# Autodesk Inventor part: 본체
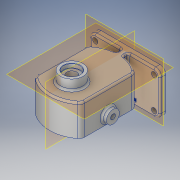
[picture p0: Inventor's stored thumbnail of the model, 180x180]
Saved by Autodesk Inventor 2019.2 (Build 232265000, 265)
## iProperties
Created: 2019-03
Part Number: 본체
Material: 알루미늄 6061
Document SubType Name: Modeling
Designer: User
Density: 2.7 g/cm^3
Appearance: 알루미늄 - 평지
Mass: 1187.2 g
Surface Area: 719.418 cm^2
Volume: 439.702 cm^3
Author: User
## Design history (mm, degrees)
sketch "스케치1"
  geometry: L1 (-84, 0)-(84, 0) reference; L2 (0, 14.6)-(0, -87.6) reference; L3 (-60, -73)-(60, -73); L4 (60, -73)-(60, 0); L5 (60, 0)-(-60, 0); L6 (-60, 0)-(-60, -73); L7 (-60, -73)-(60, 0); L8 (60, -73)-(-60, 0); 2 further points
  constraints: 12 end point, 3 midpoint, 2 parallel, 1 horizontal, 1 perpendicular, 1 point on line
  dimensions: "d0" = 73 distance of L3.end L4.end; "d1" = 120 distance of L3.start L3.end
extrude "돌출1" new body sketch "스케치1" distance "d2" = 10; taper "d3" = 0 deg
sketch "스케치3"
  geometry: L1 (0, 0)-(-43, 0); L2 (-43, 0)-(-43, 90.686); L3 (-43, 90.686)-(0, 90.686); L4 (0, 90.686)-(0, 0)
  constraints: 8 end point, 2 parallel, 1 horizontal, 1 perpendicular
  dimensions: "d6" = 43 distance of L1.start L1.end; "d7" = 90.68632 distance between parallel lines of L1 L3
extrude "돌출2" join sketch "스케치3" stored distance "d8" = 12; taper "d9" = 0 deg
sketch "스케치4"
  geometry: L1 (-40, 112.721)-(-40, 23.279); L2 (40, 112.721)-(40, 23.279); L3 (-200.879, 0)-(139.916, 0) reference; L4 (0, -37.6)-(0, 155.6) reference; L5 (91.231, 128)-(-152.194, 128); L6 (40, 112.721)-(-40, 112.721); L7 (40, 23.279)-(-40, 23.279); L8 (-60, -10)-(60, -10) reference; A1 r 60 centre (0, 68) between (40, 112.721) and (-40, 112.721); A2 r 60 centre (0, 68) between (-40, 23.279) and (40, 23.279); 1 further point
  constraints: 10 end point, 4 point on circle, 2 centre point, 2 horizontal, 2 perpendicular, 1 parallel, 1 point on line, 1 tangent, 1 other
  dimensions: "d23" = 80 distance between parallel lines of L2 L1; "d25" = 60 radius of A1; "d26" = 60 radius of A2; "d29" = 138 distance between parallel lines of L8 L5
extrude "돌출3" join sketch "스케치4" distance "d14" = 53; taper "d15" = 0 deg
sketch "스케치5"
  geometry: L1 (24, 90)-(24, 46); L2 (-24, 90)-(-24, 46); L3 (0, 155.6)-(0, -37.6) reference; L4 (-78.912, 68)-(103.855, 68); L5 (60, -10)-(-60, -10) reference; A1 r 24 centre (0, 90) between (24, 90) and (-24, 90); A2 r 24 centre (0, 46) between (-24, 46) and (24, 46); 1 further point
  constraints: 6 end point, 4 point on circle, 4 tangent, 2 centre point, 2 point on line, 1 horizontal, 1 parallel
  dimensions: "d21" = 44 distance of A2.centre A1.centre; "d22" = 24 radius of A1; "d27" = 22 distance from line of L1.end L4; "d28" = 78 distance between parallel lines of L5 L4
extrude "돌출4" cut sketch "스케치5" distance "d30" = 29; taper "d31" = 0 deg
sketch "스케치6"
  geometry: A1 r 24 centre (0, 90) between (24, 90) and (-24, 90) reference; 2 further points
  constraints: 1 coincident
hole "구멍1" sketch "스케치6" at (0, 90) diameter "d32" = 25; stored, may be unused: countersink angle "d36" = 82 deg, drill point angle "d38" = 0 deg; dims "d33" = 12, "d34" = 3.023, "d35" = 2, "d37" = 15
sketch "스케치7"
  geometry: A1 r 24 centre (0, 46) between (-24, 46) and (24, 46) reference; 2 further points
  constraints: 1 coincident
hole "구멍2" sketch "스케치7" at (0, 46) diameter "d39" = 25; stored, may be unused: countersink angle "d43" = 82 deg, drill point angle "d45" = 0 deg; dims "d40" = 12, "d41" = 3.023, "d42" = 2, "d44" = 15
sketch "스케치9"
  geometry: C1 r 19 at (60, -100); C2 r 12.5 at (60, -100) reference; 1 further point
  constraints: 1 centre point, 1 concentric
  dimensions: "d47" = 38 diameter of C1
extrude "돌출5" join sketch "스케치9" distance "d48" = 17; taper "d49" = 0 deg
sketch "스케치10"
  geometry: C1 r 19 at (0, 0) reference; 2 further points
  constraints: 1 coincident
hole "구멍3" sketch "스케치10" at (0, 0) diameter "d50" = 17; stored, may be unused: countersink angle "d54" = 82 deg, drill point angle "d56" = 0 deg; dims "d51" = 12, "d52" = 28, "d53" = 7.3, "d55" = 15
sketch "스케치11"
  geometry: L1 (-24, 46)-(-24, 90) reference; L2 (24, 90)-(24, 46) reference; L3 (0, 90)-(0, 121); A1 r 24 centre (0, 90) between (24, 90) and (-24, 90) reference; A2 r 24 centre (0, 46) between (-24, 46) and (24, 46) reference; 1 further point
  constraints: 2 end point, 1 vertical
  dimensions: "d57" = 31 distance of L3.start L3.end
hole "구멍4" sketch "스케치11" at (0, 121) diameter "d58" = 4.134; stored, may be unused: countersink angle "d62" = 82 deg, drill point angle "d64" = 118 deg; dims "d59" = 10, "d60" = 3.023, "d61" = 7.3, "d63" = 12
sketch "스케치12"
  geometry: L1 (24, 90)-(24, 46) reference; L2 (-24, 46)-(-24, 90) reference; L3 (0, 90)-(-31, 90); L4 (-31, 90)-(-31, 46); A1 r 24 centre (0, 90) between (24, 90) and (-24, 90) reference; A2 r 24 centre (0, 46) between (-24, 46) and (24, 46) reference; 1 further point
  constraints: 4 end point, 1 horizontal, 1 perpendicular
  dimensions: "d65" = 44 distance of L3.end L4.end; "d66" = 31 distance of L3.start L3.end
hole "구멍5" sketch "스케치12" at (-31, 90), (-31, 46) diameter "d67" = 4.134; stored, may be unused: countersink angle "d71" = 82 deg, drill point angle "d73" = 118 deg; dims "d68" = 10, "d69" = 3.023, "d70" = 7.3, "d72" = 12
sketch "스케치14"
  geometry: L1 (104.721, 0)-(104.721, -53) reference; L2 (44.721, 58.042)-(44.721, -160.194); L3 (-23.279, -73)-(-33.279, -73) reference; L4 (89.443, -53)-(0, -53) reference; C1 r 11 at (44.721, -39); 1 further point
  constraints: 2 end point, 1 centre point, 1 point on line, 1 vertical
  dimensions: "d77" = 22 diameter of C1; "d78" = 60 distance between parallel lines of L2 L1; "d117" = 14 distance from line of C1.centre L4
extrude "돌출6" join sketch "스케치14" distance "d80" = 8; taper "d81" = 0 deg
sketch "스케치15"
  geometry: C1 r 11 at (0, 0) reference; 2 further points
  constraints: 1 coincident
hole "구멍6" sketch "스케치15" at (0, 0) diameter "d82" = 8.376; stored, may be unused: countersink angle "d86" = 82 deg, drill point angle "d88" = 118 deg; dims "d83" = 40, "d84" = 3.023, "d85" = 7.3, "d87" = 27.3
fillet "모깎기1" dims "d89" = 10
fillet "모깎기2" dims "d90" = 3
fillet "모깎기3" dims "d91" = 3
fillet "모깎기4" dims "d92" = 3
fillet "모깎기5" dims "d93" = 10
fillet "모깎기6" dims "d94" = 3
fillet "모깎기7" dims "d95" = 3
fillet "모깎기8" dims "d96" = 0.5
chamfer "모따기2" distance "d100" = 1; stored, may be unused: second distance "d101" = 2, angle "d102" = 30 deg
sketch "스케치16"
  geometry: L1 (-50, -73)-(50, -73) reference; L2 (-60, -10)-(-60, -63) reference; 2 further points
  constraints: 1 other
  dimensions: "d103" = 10 distance from line of L1 point (0, -63); "d104" = 60 distance from line of point (0, -63) L2
feature "엠보싱1" sketch "스케치16" dims "d23" = 80, "d25" = 60, "d26" = 60, "d29" = 138, "d105" = 0.5, "d106" = 0
sketch "스케치17"
  geometry: C1 r 4.5 at (-50, -10); C2 r 4.5 at (-50, -63); A1 r 10 centre (-50, -10) between (-50, 0) and (-60, -10) reference; A2 r 10 centre (-50, -63) between (-60, -63) and (-50, -73) reference; 1 further point
  constraints: 2 centre point, 2 concentric
  dimensions: "d107" = 9 diameter of C1; "d108" = 9 diameter of C2
extrude "돌출7" cut sketch "스케치17" distance "d109" = 10; taper "d110" = 0 deg
chamfer "모따기3" distance "d111" = 1; stored, may be unused: second distance "d112" = 2, angle "d113" = 45 deg
chamfer "모따기4" distance "d114" = 0.7; stored, may be unused: second distance "d115" = 2, angle "d116" = 30 deg
node "솔리드1"
mirror "미러1"
pattern_linear "직사각형 패턴1" dims "d76" = 106
mirror "미러2"
mirror "미러3"
other parameters: "d24" = 83.65028
